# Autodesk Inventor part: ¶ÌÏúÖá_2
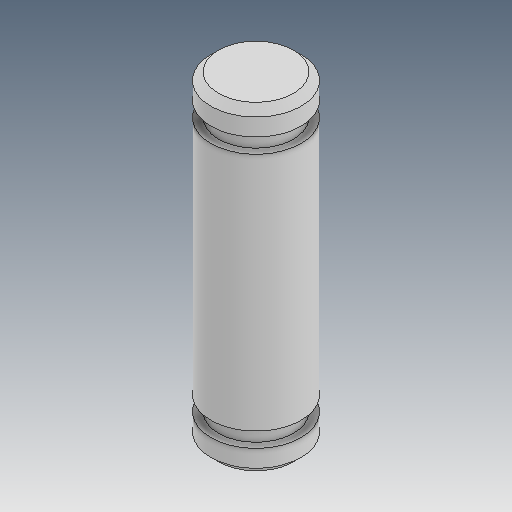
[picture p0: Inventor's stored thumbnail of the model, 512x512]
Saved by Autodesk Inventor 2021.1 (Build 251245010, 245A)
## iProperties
Created: 2019-04
Part Number: ¶ÌÏúÖá_2
Material: Ogólny
Document SubType Name: Modeling
Designer: user
Density: 1 g/cm^3
Appearance: Domyślna
Author: user
Revision Number: ÈÎºÎ
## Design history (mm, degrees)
feature "ÊäÈë1"
node "Bryła1"
